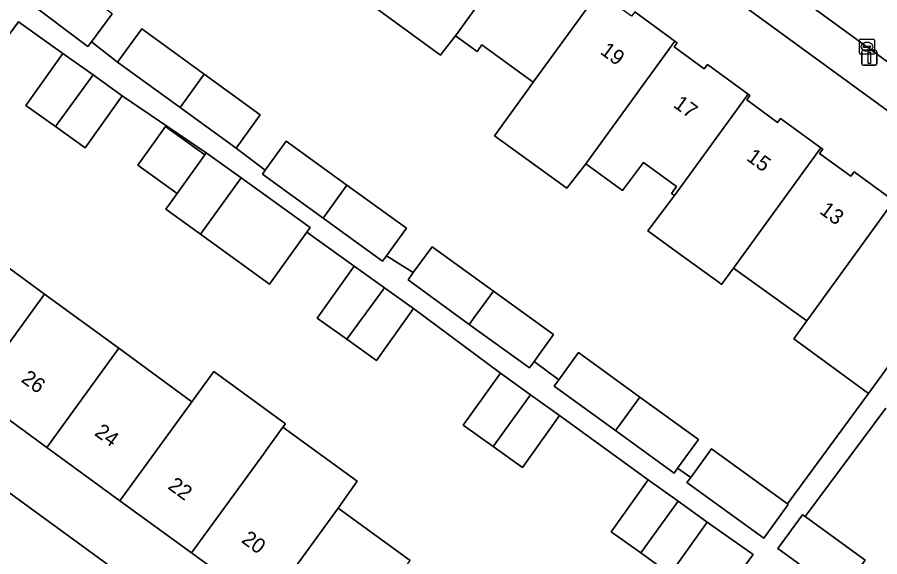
# Model space of a CAD drawing. Extents: x 159674 to 160531, y 382172 to 382904.
# Drawn here: x 160017.6 to 160074.9, y 382378.1 to 382413.9 of the extents above; entities that cross this region are included whole.
import ezdxf

# ---------------------------------------------------------------- set-up
doc = ezdxf.new("R2010")
doc.units = 0
for name, color, linetype in [('IMGEO_Erf', 7, 'Continuous'), ('IMGEO_Kolk', 7, 'Continuous'), ('IMGEO_Lichtmast', 7, 'Continuous'), ('IMGEO_Pand', 7, 'Continuous'), ('IMGEO_Pand_nummerreeks', 7, 'Continuous'), ('IMGEO_Rijbaan_lokaal_open', 7, 'Continuous'), ('IMGEO_Voetpad_open', 7, 'Continuous')]:
    doc.layers.add(name, color=color, linetype=linetype)

msp = doc.modelspace()

# ---------------------------------------------------------------- linework, layer by layer
at = {"layer": 'IMGEO_Erf'}
for points in [[(160083.531, 382401.81), (160034.768, 382437.312)], [(160023.931, 382414.118), (160022.545, 382412.269), (160024.282, 382410.917), (160025.893, 382413.135), (160030.039, 382410.124), (160033.763, 382407.419), (160032.152, 382405.201), (160034.085, 382403.738), (160035.489, 382405.671), (160039.519, 382402.757), (160043.473, 382399.898), (160042.143, 382398.067), (160043.92, 382396.947), (160045.171, 382398.67), (160049.246, 382395.723), (160053.241, 382392.834), (160051.944, 382391.049), (160053.583, 382389.829), (160054.896, 382391.637), (160058.971, 382388.69), (160062.863, 382385.876), (160061.48, 382383.971), (160062.351, 382383.361), (160063.725, 382385.253), (160068.773, 382381.603), (160074.153, 382388.929), (160069.187, 382392.545), (160070.065, 382393.754), (160065.185, 382397.247), (160064.398, 382396.164), (160064.228, 382396.288), (160061.629, 382398.181), (160059.51, 382399.725), (160061.268, 382402.066), (160061.078, 382402.204), (160061.406, 382402.654), (160059.203, 382404.258), (160057.817, 382402.39), (160055.378, 382404.167), (160054.119, 382402.544), (160049.32, 382406.038), (160051.57, 382409.148), (160051.892, 382409.591), (160048.483, 382412.073), (160048.156, 382411.625), (160046.719, 382412.671), (160045.904, 382411.621), (160045.725, 382411.376), (160040.904, 382414.902)], [(160058.626, 382414.263), (160061.297, 382412.318), (160061.448, 382412.208), (160061.245, 382411.93), (160063.252, 382410.469), (160063.461, 382410.756), (160066.154, 382408.795), (160066.282, 382408.702), (160066.069, 382408.41), (160068.119, 382406.918), (160068.311, 382407.18), (160070.984, 382405.234), (160071.118, 382405.136), (160070.91, 382404.851), (160072.976, 382403.347), (160073.194, 382403.648), (160075.846, 382401.717)], [(160058.348, 382367.13), (160066.486, 382378.229), (160063.45, 382380.395), (160060.988, 382376.944), (160059.027, 382378.343), (160057.054, 382379.75), (160059.516, 382383.202), (160053.639, 382387.461), (160051.177, 382384.01), (160049.217, 382385.408), (160047.243, 382386.816), (160049.705, 382390.268), (160043.939, 382394.574), (160041.477, 382391.123), (160039.516, 382392.522), (160037.543, 382393.929), (160040.005, 382397.381), (160036.855, 382399.629), (160034.38, 382396.189), (160029.793, 382399.49), (160027.477, 382401.157), (160028.231, 382402.205), (160025.623, 382404.082), (160027.471, 382406.649), (160030.079, 382404.772), (160030.175, 382404.905), (160024.587, 382408.692), (160022.125, 382405.241), (160020.164, 382406.639), (160018.191, 382408.047), (160020.653, 382411.499), (160017.707, 382413.601), (160009.634, 382402.696)], [(160014.631, 382399.046), (160019.438, 382395.527), (160024.375, 382391.93), (160029.21, 382388.368), (160030.674, 382390.378), (160035.429, 382386.913), (160035.267, 382386.69), (160040.185, 382383.107), (160038.941, 382381.325), (160043.71, 382377.851)], [(160075.306, 382387.949), (160069.951, 382380.751), (160073.931, 382377.873), (160072.457, 382375.844), (160072.29, 382375.614), (160089.238, 382363.297)]]:
    msp.add_lwpolyline(points, dxfattribs=at)
msp.add_lwpolyline([(160029.188, 382378.345), (160024.432, 382381.81), (160019.577, 382385.347), (160014.641, 382388.943), (160009.826, 382392.451), (160004.805, 382396.109), (160002.502, 382392.948), (160051.264, 382357.423), (160053.567, 382360.584), (160048.682, 382364.143), (160043.927, 382367.607), (160038.909, 382371.263), (160034.141, 382374.737)], close=True, dxfattribs=at)
at = {"layer": 'IMGEO_Kolk'}
for p, q in [((160073.629, 382412.442), (160074.481, 382412.442)), ((160073.554, 382411.516), (160073.554, 382412.368)), ((160073.813, 382411.936), (160073.813, 382411.948)), ((160074.251, 382411.899), (160073.853, 382411.899)), ((160073.856, 382411.985), (160074.254, 382411.985)), ((160074.042, 382412.222), (160074.067, 382412.222)), ((160074.297, 382411.948), (160074.297, 382411.936)), ((160074.555, 382412.368), (160074.555, 382411.516)), ((160074.481, 382411.442), (160073.629, 382411.442)), ((160074.065, 382411.662), (160074.04, 382411.662))]:
    msp.add_line(p, q, dxfattribs=at)
for points in [[(160073.629, 382412.442), (160074.481, 382412.442)], [(160073.554, 382411.516), (160073.554, 382412.368)], [(160074.555, 382412.368), (160074.555, 382411.516)], [(160074.481, 382411.442), (160073.629, 382411.442)]]:
    msp.add_lwpolyline(points, dxfattribs=at)
for centre, radius, start, end in [((160073.631, 382412.366), 0.0765, 91.552, 178.448), ((160073.631, 382412.366), 0.0765, 91.552, 178.448), ((160074.479, 382412.366), 0.0765, 1.552, 88.448), ((160074.479, 382412.366), 0.0765, 1.552, 88.448), ((160073.853, 382411.945), 0.0403, 85.8775, 175.7526), ((160073.85, 382411.935), 0.0366, 178.938, 274.7102), ((160074.254, 382411.942), 0.043, 264.8664, 352.4533), ((160074.258, 382411.947), 0.0386, 1.7309, 96.639), ((160073.631, 382411.518), 0.0765, 181.552, 268.448), ((160073.631, 382411.518), 0.0765, 181.552, 268.448), ((160074.479, 382411.518), 0.0765, 271.552, 358.448), ((160074.479, 382411.518), 0.0765, 271.552, 358.448)]:
    msp.add_arc(centre, radius, start, end, dxfattribs=at)
for centre, major_axis, ratio, start_param, end_param in [((160074.041, 382411.942), (-0.387, 0.002), 0.722429, 4.712389, 7.853982), ((160074.066, 382411.942), (-0.39, 0.002), 0.717154, 1.570796, 4.712389)]:
    msp.add_ellipse(centre, major_axis=major_axis, ratio=ratio, start_param=start_param, end_param=end_param, dxfattribs=at)
at = {"layer": 'IMGEO_Lichtmast'}
for p, q in [((160073.715, 382410.812), (160073.715, 382411.612)), ((160073.715, 382411.612), (160073.715, 382410.812)), ((160073.815, 382411.712), (160074.605, 382411.712)), ((160074.605, 382411.712), (160073.815, 382411.712)), ((160074.705, 382411.612), (160074.705, 382410.812)), ((160074.705, 382410.812), (160074.705, 382411.612)), ((160074.605, 382410.712), (160073.815, 382410.712)), ((160073.815, 382410.712), (160074.605, 382410.712))]:
    msp.add_line(p, q, dxfattribs=at)
msp.add_lwpolyline([(160074.135, 382411.587), (160074.285, 382411.587), (160074.285, 382410.837), (160074.135, 382410.837), (160074.135, 382411.587)], dxfattribs=at)
for centre, start, end in [((160073.815, 382411.612), 90, 180), ((160073.815, 382411.612), 90, 180), ((160074.605, 382411.612), 0, 90), ((160074.605, 382411.612), 360, 90), ((160073.815, 382410.812), 180, 270), ((160073.815, 382410.812), 180, 270), ((160074.605, 382410.812), 270, 0), ((160074.605, 382410.812), 270, 0)]:
    msp.add_arc(centre, 0.1, start, end, dxfattribs=at)
at = {"layer": 'IMGEO_Pand'}
for points in [[(160051.563, 382419.341), (160048.913, 382421.27), (160048.7, 382420.976), (160046.62, 382422.49), (160046.805, 382422.744), (160046.682, 382422.833), (160042.201, 382416.661), (160040.904, 382414.902), (160045.725, 382411.376), (160045.904, 382411.621), (160046.719, 382412.671)], [(160056.422, 382415.82), (160053.804, 382417.726), (160053.62, 382417.473), (160051.485, 382419.028), (160051.661, 382419.269), (160051.563, 382419.341), (160046.719, 382412.671), (160048.156, 382411.625), (160048.483, 382412.073), (160051.892, 382409.591)], [(160020.135, 382416.965), (160019.913, 382417.132), (160018.288, 382414.965), (160022.306, 382411.951), (160022.545, 382412.269), (160023.931, 382414.118)], [(160061.297, 382412.318), (160058.626, 382414.263), (160058.412, 382413.969), (160056.422, 382415.419), (160056.613, 382415.681), (160056.422, 382415.82), (160051.892, 382409.591), (160051.57, 382409.148), (160049.32, 382406.038), (160054.119, 382402.544), (160055.378, 382404.167)], [(160028.429, 382407.905), (160030.039, 382410.124), (160025.893, 382413.135), (160024.282, 382410.917)], [(160055.378, 382404.167), (160057.817, 382402.39), (160059.203, 382404.258), (160061.406, 382402.654), (160061.078, 382402.204), (160061.268, 382402.066), (160066.154, 382408.795), (160063.461, 382410.756), (160063.252, 382410.469), (160061.245, 382411.93), (160061.448, 382412.208), (160061.297, 382412.318)], [(160020.164, 382406.639), (160022.661, 382410.066), (160020.653, 382411.499), (160018.191, 382408.047)], [(160028.429, 382407.905), (160032.152, 382405.201), (160033.763, 382407.419), (160030.039, 382410.124)], [(160020.164, 382406.639), (160022.125, 382405.241), (160024.587, 382408.692), (160022.661, 382410.066)], [(160070.984, 382405.234), (160068.311, 382407.18), (160068.119, 382406.918), (160066.069, 382408.41), (160066.282, 382408.702), (160066.154, 382408.795), (160061.268, 382402.066), (160059.51, 382399.725), (160061.629, 382398.181), (160064.228, 382396.288), (160064.398, 382396.164), (160065.185, 382397.247)], [(160030.079, 382404.772), (160027.471, 382406.649), (160025.623, 382404.082), (160028.231, 382402.205)], [(160034.085, 382403.738), (160033.907, 382403.493), (160037.931, 382400.57), (160038.152, 382400.874), (160039.519, 382402.757), (160035.489, 382405.671)], [(160075.846, 382401.717), (160073.194, 382403.648), (160072.976, 382403.347), (160070.91, 382404.851), (160071.118, 382405.136), (160070.984, 382405.234), (160065.185, 382397.247), (160070.065, 382393.754)], [(160032.484, 382403.242), (160030.175, 382404.905), (160030.079, 382404.772), (160028.231, 382402.205), (160027.477, 382401.157), (160029.793, 382399.49)], [(160037.077, 382399.937), (160032.484, 382403.242), (160029.793, 382399.49), (160034.38, 382396.189), (160036.855, 382399.629)], [(160039.519, 382402.757), (160038.152, 382400.874), (160037.931, 382400.57), (160041.879, 382397.703), (160042.143, 382398.067), (160043.473, 382399.898)], [(160080.833, 382398.104), (160078.087, 382400.103), (160077.906, 382399.854), (160075.84, 382401.359), (160076.013, 382401.596), (160075.846, 382401.717), (160070.065, 382393.754), (160069.187, 382392.545), (160074.153, 382388.929), (160075.387, 382390.624), (160077.89, 382394.062)], [(160019.438, 382395.527), (160014.631, 382399.046), (160009.826, 382392.451), (160014.641, 382388.943)], [(160043.92, 382396.947), (160043.574, 382396.471), (160047.643, 382393.516), (160047.968, 382393.962), (160049.246, 382395.723), (160045.171, 382398.67)], [(160042.012, 382395.949), (160040.005, 382397.381), (160037.543, 382393.929), (160039.516, 382392.522)], [(160042.012, 382395.949), (160039.516, 382392.522), (160041.477, 382391.123), (160043.939, 382394.574)], [(160024.375, 382391.93), (160019.438, 382395.527), (160014.641, 382388.943), (160019.577, 382385.347)], [(160049.246, 382395.723), (160047.968, 382393.962), (160047.643, 382393.516), (160051.632, 382390.619), (160051.944, 382391.049), (160053.241, 382392.834)], [(160029.21, 382388.368), (160024.375, 382391.93), (160019.577, 382385.347), (160024.432, 382381.81)], [(160053.583, 382389.829), (160053.285, 382389.418), (160057.354, 382386.462), (160057.622, 382386.831), (160058.971, 382388.69), (160054.896, 382391.637)], [(160033.965, 382384.903), (160034.283, 382385.339), (160035.267, 382386.69), (160035.429, 382386.913), (160030.674, 382390.378), (160029.21, 382388.368), (160024.432, 382381.81), (160029.188, 382378.345)], [(160051.714, 382388.835), (160049.705, 382390.268), (160047.243, 382386.816), (160049.217, 382385.408)], [(160051.714, 382388.835), (160049.217, 382385.408), (160051.177, 382384.01), (160053.639, 382387.461)], [(160058.971, 382388.69), (160057.622, 382386.831), (160057.354, 382386.462), (160061.24, 382383.64), (160061.48, 382383.971), (160062.863, 382385.876)], [(160038.941, 382381.325), (160040.185, 382383.107), (160035.267, 382386.69), (160034.283, 382385.339), (160033.965, 382384.903), (160029.188, 382378.345), (160034.141, 382374.737)], [(160062.351, 382383.361), (160062.1, 382383.015), (160067.195, 382379.314), (160068.828, 382381.563), (160068.773, 382381.603), (160063.725, 382385.253)], [(160061.523, 382381.77), (160059.516, 382383.202), (160057.054, 382379.75), (160059.027, 382378.343)], [(160061.523, 382381.77), (160059.027, 382378.343), (160060.988, 382376.944), (160063.45, 382380.395)], [(160043.71, 382377.851), (160038.941, 382381.325), (160034.141, 382374.737), (160038.909, 382371.263)], [(160069.951, 382380.751), (160069.768, 382380.883), (160068.138, 382378.63), (160072.29, 382375.614), (160072.457, 382375.844), (160073.931, 382377.873)]]:
    msp.add_lwpolyline(points, close=True, dxfattribs=at)
at = {"layer": 'IMGEO_Rijbaan_lokaal_open'}
msp.add_lwpolyline([(160014.616, 382455.167), (160030.935, 382443.3), (160034.415, 382440.769), (160099.29, 382393.592), (160102.339, 382391.375), (160119.102, 382379.184)], dxfattribs=at)
at = {"layer": 'IMGEO_Voetpad_open'}
for points in [[(160011.345, 382453.23), (160033.01, 382437.511), (160034.251, 382436.61), (160034.768, 382437.312), (160083.531, 382401.81), (160085.455, 382400.41), (160110.564, 382382.129), (160106.732, 382376.818), (160104.611, 382373.905), (160105.953, 382372.892), (160111.288, 382369.019), (160119.102, 382379.184), (160102.339, 382391.375), (160102.045, 382390.971), (160098.996, 382393.188), (160099.29, 382393.592), (160034.415, 382440.769)], [(160075.387, 382390.624), (160074.153, 382388.929), (160068.773, 382381.603), (160068.828, 382381.563), (160067.195, 382379.314), (160062.1, 382383.015), (160062.351, 382383.361), (160061.48, 382383.971), (160061.24, 382383.64), (160057.354, 382386.462), (160053.285, 382389.418), (160053.583, 382389.829), (160051.944, 382391.049), (160051.632, 382390.619), (160047.643, 382393.516), (160043.574, 382396.471), (160043.92, 382396.947), (160042.143, 382398.067), (160041.879, 382397.703), (160037.931, 382400.57), (160033.907, 382403.493), (160034.085, 382403.738), (160032.152, 382405.201), (160028.429, 382407.905), (160024.282, 382410.917), (160022.545, 382412.269), (160022.306, 382411.951), (160018.288, 382414.965)], [(160009.634, 382402.696), (160017.707, 382413.601), (160020.653, 382411.499), (160022.661, 382410.066), (160024.587, 382408.692), (160030.175, 382404.905), (160032.484, 382403.242), (160037.077, 382399.937), (160036.855, 382399.629), (160040.005, 382397.381), (160042.012, 382395.949), (160043.939, 382394.574), (160049.705, 382390.268), (160051.714, 382388.835), (160053.639, 382387.461), (160059.516, 382383.202), (160061.523, 382381.77), (160063.45, 382380.395), (160066.486, 382378.229), (160058.348, 382367.13)], [(160076.39, 382339.118), (160053.693, 382355.653), (160051.264, 382357.423), (160002.502, 382392.948)], [(160089.238, 382363.297), (160072.29, 382375.614), (160068.138, 382378.63), (160069.768, 382380.883), (160069.951, 382380.751), (160075.306, 382387.949)]]:
    msp.add_lwpolyline(points, dxfattribs=at)

# ---------------------------------------------------------------- texts
at = {"layer": 'IMGEO_Pand_nummerreeks'}
for s, rotation, p in [('19', 323.9896, (160056.278, 382411.513)), ('17', 323.9907, (160061.133, 382407.984)), ('15', 323.9896, (160065.989, 382404.456)), ('13', 323.9896, (160070.844, 382400.927)), ('26', 323.9266, (160017.811, 382389.752)), ('24', 323.9266, (160022.687, 382386.199)), ('22', 323.9266, (160027.561, 382382.649)), ('20', 323.9266, (160032.442, 382379.092))]:
    msp.add_text(s, height=1, rotation=rotation, dxfattribs=at).set_placement(p)

doc.saveas('drawing.dxf')
